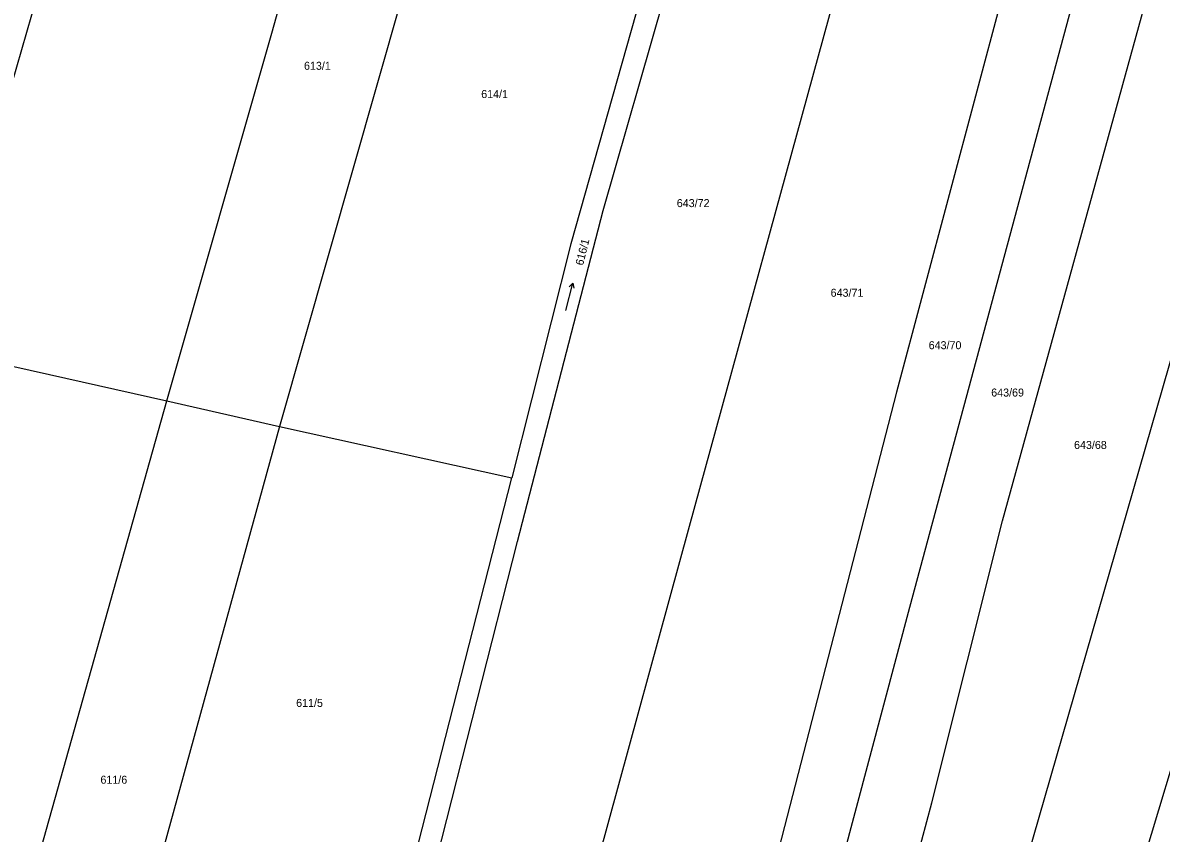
# Model space of a CAD drawing. Extents: x -701211 to -698780, y -1014269 to -1012378.
# Drawn here: x -700355.1 to -700113.3, y -1013759.8 to -1013587.7 of the extents above; entities that cross this region are included whole.
import ezdxf
from ezdxf.enums import TextEntityAlignment as Align

# ---------------------------------------------------------------- set-up
doc = ezdxf.new("R2010")
doc.units = 0
doc.header["$LTSCALE"] = 0.68
doc.layers.add('1', color=7, linetype='Continuous', lineweight=25)
doc.layers.add('3', color=7, linetype='Continuous', lineweight=25)
doc.layers.add('2', color=7, linetype='Continuous')

msp = doc.modelspace()

# ---------------------------------------------------------------- linework, layer by layer
at = {"layer": '1'}
for p, q in [((-700302.17, -1013589.88), (-700266.64, -1013462.93)), ((-700201, -1013501.17), (-700238.69, -1013634.62)), ((-700213.5, -1013694.58), (-700162.62, -1013509.15)), ((-700129.45, -1013516.02), (-700169.53, -1013666.16)), ((-700231.82, -1013627.52), (-700207.23, -1013541.52)), ((-700271.16, -1013570.27), (-700300.53, -1013673.39)), ((-700357.38, -1013600.69), (-700349.66, -1013573.99)), ((-700166.66, -1013711.75), (-700129.69, -1013574.41)), ((-700146.99, -1013693.42), (-700116.14, -1013581.53)), ((-700324.49, -1013667.95), (-700302.17, -1013589.88)), ((-700250.03, -1013697.82), (-700231.82, -1013627.52)), ((-700152.11, -1013801.13), (-700103.11, -1013630.91)), ((-700238.69, -1013634.62), (-700251.21, -1013684.29)), ((-700372.54, -1013657.2), (-700324.49, -1013667.95)), ((-700169.53, -1013666.16), (-700200.4, -1013785.73)), ((-700375.69, -1013850.23), (-700324.49, -1013667.95)), ((-700324.49, -1013667.95), (-700300.53, -1013673.39)), ((-700300.53, -1013673.39), (-700350.86, -1013856.14)), ((-700300.53, -1013673.39), (-700251.21, -1013684.29)), ((-700092.33, -1013683.22), (-700148.1, -1013868.52)), ((-700275.41, -1013779.04), (-700251.21, -1013684.29)), ((-700249.19, -1013825.04), (-700213.5, -1013694.58)), ((-700161.98, -1013753.3), (-700146.99, -1013693.42)), ((-700273.23, -1013789.41), (-700250.03, -1013697.82)), ((-700194.71, -1013816.74), (-700166.66, -1013711.75)), ((-700178.73, -1013814.96), (-700161.98, -1013753.3))]:
    msp.add_line(p, q, dxfattribs=at)
at = {"layer": '3'}
msp.add_line((-700238.272, -1013642.955), (-700238.022, -1013644.024), dxfattribs=at)
msp.add_lwpolyline([(-700239.723, -1013648.776), (-700238.272, -1013642.955), (-700238.995, -1013643.781)], dxfattribs=at)

# ---------------------------------------------------------------- texts
at = {"layer": '2'}
for s, p in [('613/1', (-700292.49, -1013597.665)), ('614/1', (-700254.86, -1013603.665)), ('643/72', (-700212.69, -1013626.825)), ('643/71', (-700180.02, -1013645.865)), ('643/70', (-700159.2, -1013657.005)), ('643/69', (-700145.92, -1013667.055)), ('643/68', (-700128.33, -1013678.185))]:
    msp.add_text(s, height=1.7, dxfattribs=at).set_placement(p, align=Align.CENTER)
msp.add_text('616/1', height=1.7, rotation=76, dxfattribs=at).set_placement((-700235.4007, -1013636.5671), align=Align.CENTER)
for s, p in [('611/5', (-700297, -1013732.965)), ('611/6', (-700338.56, -1013749.275))]:
    msp.add_text(s, height=1.7, dxfattribs=at).set_placement(p)

doc.saveas('drawing.dxf')
